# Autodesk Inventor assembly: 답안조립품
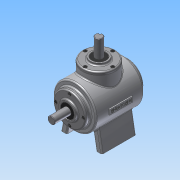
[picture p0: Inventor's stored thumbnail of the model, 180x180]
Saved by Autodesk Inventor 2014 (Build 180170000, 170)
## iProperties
Created: 2015-01
Part Number: 답안조립품
Document SubType Name: Assembly
Designer: user
Author: user
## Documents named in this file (15)
- C:\Users\user\Desktop\450105v1025\답안조립품.iam
- C:\Users\user\Desktop\450105v1025\본체.ipt
- C:\Users\user\Desktop\450105v1025\메인 베벨기어.ipt
- C:\Users\user\Desktop\450105v1025\메인 축.ipt
- 메인 축.ipt
- C:\Users\user\Desktop\450105v1025\베어링 6203.ipt
- C:\Users\user\Desktop\450105v1025\오일실.ipt
- C:\Users\user\Desktop\450105v1025\커버.ipt
- C:\Users\user\Desktop\450105v1025\키 5x5.ipt
- C:\Users\user\Desktop\450105v1025\서브 베벨기어.ipt
- C:\Users\user\Desktop\450105v1025\서브 축.ipt
- 서브 축.ipt
- C:\Users\user\Desktop\450105v1025\키 4x4.ipt
- C:\Users\user\Desktop\450105v1025\커버2.ipt
- C:\Users\user\Desktop\450105v1025\M4.ipt
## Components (12 placed, 1 different names)
1. M4:1 — 각도:5
2. M4:3 — 각도:6
3. M4:4
4. M4:5
5. M4:6
6. M4:7
7. M4:8
8. M4:9
9. M4:2 — 각도:7
10. M4:10
11. M4:11
12. M4:12
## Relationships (3: Angle 3)
- 각도:5 [Angle]: M4:1
- 각도:6 [Angle]: M4:3
- 각도:7 [Angle]: M4:2
